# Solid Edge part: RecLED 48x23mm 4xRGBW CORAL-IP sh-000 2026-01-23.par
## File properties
Author: robert.pupel
Template: iso metric part.par
Last saved by: robert.pupel
Revision: 3
Application: Solid Edge
Gęstość: 0.000 kg/m^3
Dokładność: 0.990
Username: robert.pupel
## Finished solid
Body 1: solid body, 920 faces, 2484 edges, 1648 vertices.
  Faces by surface: plane 792, cylinder 118, swept 10
  Edges by curve: line 1760, spline 296, circle 240, curve on surface 188
Bounding box of the edges (mm; curved faces can reach further): 48.000 x 3.600 x 23.000, from (-24, -2, -11.5) to (24, 1.6, 11.5).
Cylindrical faces by radius (mm): R0.3071 x1, R0.3075 x1, R0.4 x48, R0.6 x16, R0.8 x8, R0.9633 x1, R0.9774 x1, R1 x4, R1.05 x2, R1.2948 x1, R1.2986 x1, R1.5308 x4, R1.5309 x4, R1.5312 x4, R1.5316 x4, R1.6 x2, R1.7414 x4, R1.7423 x4, R1.7453 x4, R1.7463 x4
Planar faces by outward normal: +x 105, +y 61, +z 101, -x 105, -y 131, -z 101, oblique 188
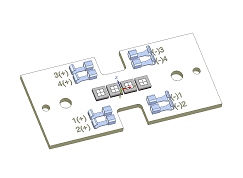
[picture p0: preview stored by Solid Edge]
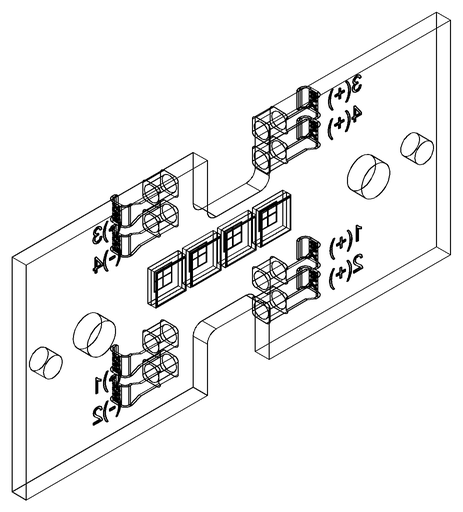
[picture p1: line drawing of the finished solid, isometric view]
